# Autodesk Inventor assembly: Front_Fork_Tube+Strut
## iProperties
Created: 2005-03
Part Number: Front_Fork_Tube+Strut
Document SubType Name: Assembly
Designer: Admin
Stock Number: Front_Fork_Tube+Strut
Author: Admin
